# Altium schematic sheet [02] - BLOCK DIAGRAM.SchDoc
size A3; DocumentNumber: 2; SheetNumber: 2; SheetTotal: 5
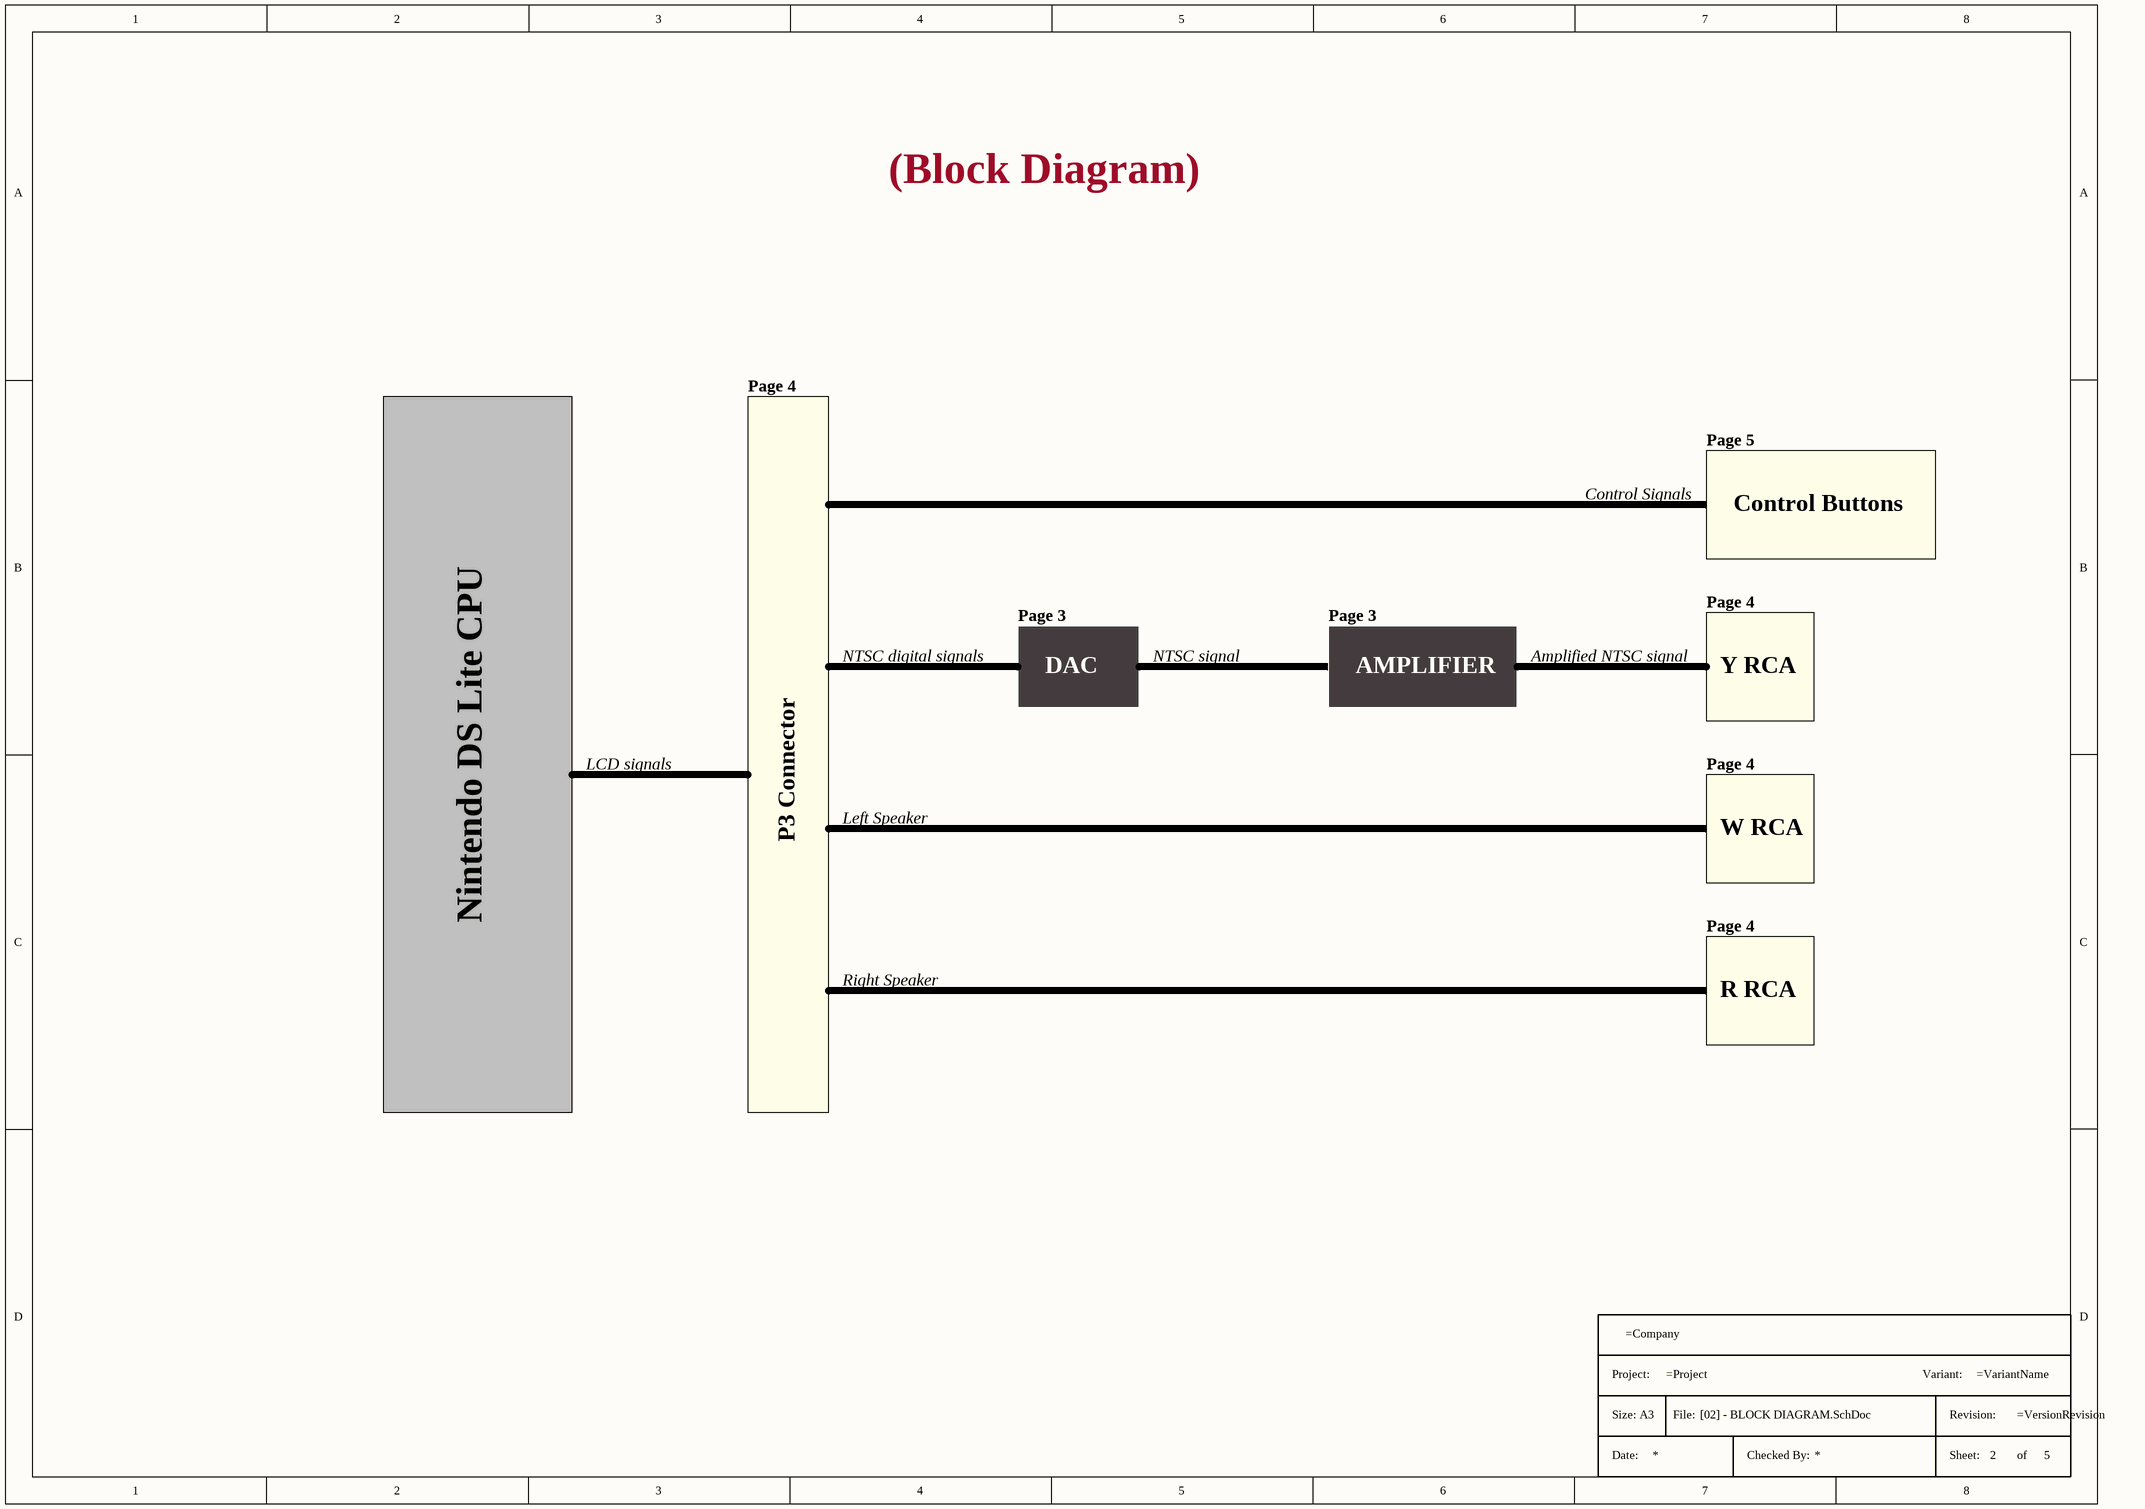
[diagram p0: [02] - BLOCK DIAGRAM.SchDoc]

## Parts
*  Title Block A3  (value not drawn)  (graphical)

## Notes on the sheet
- (Block Diagram)
- Page 4
- Page 5
- Control Signals
- Control Buttons
- Page 3
- NTSC digital signals
- DAC
- NTSC signal
- AMPLIFIER
- Amplified NTSC signal
- Y RCA
- LCD signals
- P3 Connector
- Left Speaker
- W RCA
- Nintendo DS Lite CPU
- Right Speaker
- R RCA
- CLOCKS (CPU & PCIE)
